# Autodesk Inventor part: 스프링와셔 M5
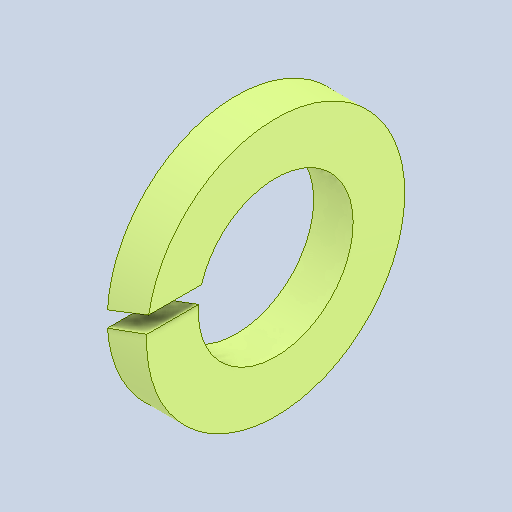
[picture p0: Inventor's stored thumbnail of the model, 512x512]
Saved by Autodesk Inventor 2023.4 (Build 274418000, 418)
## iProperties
Created: 2024-09
Part Number: 스프링와셔 M5
Material: 강철, 연강
Description: 스프링 잠금 와셔
Document SubType Name: Modeling
Designer: 11
Density: 7.85 g/cm^3
Appearance: 기본값
Author: jhkim
Sending System: Autodesk Inventor 2025
Preprocessor: ST-DEVELOPER v20
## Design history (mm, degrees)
node "스프링와셔 M51"
node "솔리드1"
body "Solid1"
